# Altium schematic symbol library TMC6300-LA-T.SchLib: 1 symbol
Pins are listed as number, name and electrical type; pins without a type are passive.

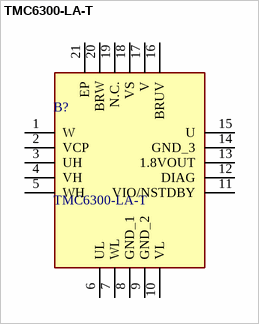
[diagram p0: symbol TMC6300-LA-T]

## TMC6300-LA-T
designator B?
Highly Efficient Low Voltage, Zero Standby Current Driver for 3-Phase BLDC/PMSM Motors up to 2A peak, Triple Half-Bridge with separate HS and LS control signals; Manufacturer_Name: Analog Devices; Geometry.Height: 0.9mm
footprint QFN40P300X300X90-21N
pins: 1 W, 2 VCP, 3 UH, 4 VH, 5 WH, 6 UL, 7 WL, 8 GND_1, 9 GND_2, 10 VL, 11 VIO/NSTDBY, 12 DIAG, 13 1.8VOUT, 14 GND_3, 15 U, 16 BRUV, 17 V, 18 VS, 19 N.C., 20 BRW, 21 EP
